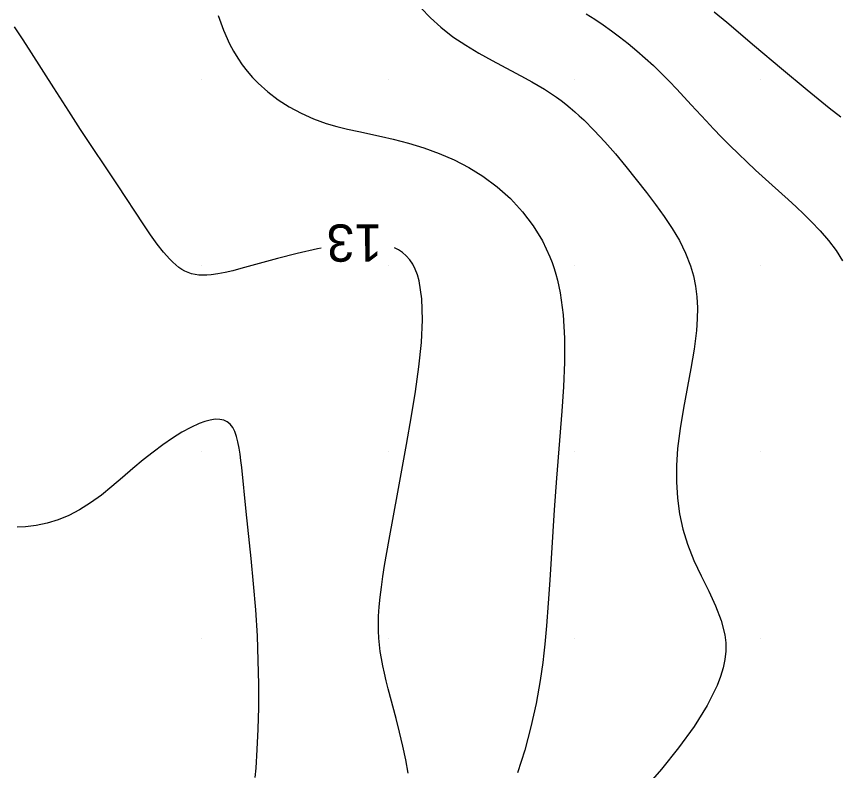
# Model space of a CAD drawing. Extents: x 2602990 to 2605851, y 618069 to 619180.
# Drawn here: x 2603060.04 to 2603104.07, y 618502.9 to 618543.37 of the extents above; entities that cross this region are included whole.
import ezdxf

# ---------------------------------------------------------------- set-up
doc = ezdxf.new("R2010")
doc.units = 0
for name, color, linetype in [('DTM Contours Major', 7, 'Continuous'), ('DTM Contours Minor', 7, 'Continuous'), ('DTM Contours Minor Text', 7, 'Continuous'), ('Exist DTM QL2 LIDAR Elevation Point', 7, 'Continuous')]:
    doc.layers.add(name, color=color, linetype=linetype)

msp = doc.modelspace()

# ---------------------------------------------------------------- linework, layer by layer
at = {"layer": 'DTM Contours Major'}
msp.add_lwpolyline([(2603097.499, 618543.623), (2603098.17, 618543.065), (2603099.669, 618541.793), (2603101.108, 618540.573), (2603102.492, 618539.429), (2603103.673, 618538.471), (2603104.295, 618537.978)], dxfattribs=at)
at = {"layer": 'DTM Contours Minor'}
for points in [[(2603081.744, 618543.84), (2603082.264, 618543.299), (2603082.825, 618542.789), (2603083.474, 618542.287), (2603084.16, 618541.826), (2603084.869, 618541.399), (2603085.586, 618541.001), (2603087.352, 618540.063), (2603087.707, 618539.868), (2603088.052, 618539.67), (2603088.388, 618539.467), (2603088.716, 618539.257), (2603089.037, 618539.038), (2603089.287, 618538.856), (2603089.533, 618538.667), (2603089.776, 618538.469), (2603090.018, 618538.262), (2603090.26, 618538.046), (2603090.501, 618537.82), (2603091.064, 618537.255), (2603091.63, 618536.643), (2603092.195, 618535.994), (2603092.757, 618535.318), (2603093.314, 618534.623), (2603093.861, 618533.92), (2603094.346, 618533.282), (2603094.811, 618532.641), (2603095.243, 618531.996), (2603095.631, 618531.342), (2603095.965, 618530.676), (2603096.232, 618529.996), (2603096.388, 618529.453), (2603096.5, 618528.898), (2603096.57, 618528.328), (2603096.6, 618527.743), (2603096.593, 618527.141), (2603096.552, 618526.52), (2603096.429, 618525.521), (2603096.254, 618524.484), (2603095.849, 618522.343), (2603095.669, 618521.26), (2603095.536, 618520.184), (2603095.478, 618519.281), (2603095.475, 618518.393), (2603095.53, 618517.523), (2603095.645, 618516.674), (2603095.823, 618515.849), (2603096.066, 618515.049), (2603096.413, 618514.184), (2603096.806, 618513.349), (2603097.207, 618512.538), (2603097.577, 618511.745), (2603097.878, 618510.963), (2603098.069, 618510.187), (2603098.116, 618509.748), (2603098.116, 618509.306), (2603098.07, 618508.86), (2603097.98, 618508.407), (2603097.845, 618507.945), (2603097.665, 618507.472), (2603097.126, 618506.388), (2603096.42, 618505.261), (2603095.587, 618504.116), (2603094.671, 618502.975), (2603093.712, 618501.86)], [(2603070.878, 618543.425), (2603071.159, 618542.639), (2603071.489, 618541.896), (2603071.699, 618541.503), (2603071.926, 618541.128), (2603072.171, 618540.771), (2603072.435, 618540.43), (2603072.717, 618540.104), (2603073.018, 618539.794), (2603073.534, 618539.331), (2603074.093, 618538.906), (2603074.691, 618538.522), (2603075.323, 618538.181), (2603075.986, 618537.885), (2603076.674, 618537.635), (2603077.243, 618537.468), (2603077.825, 618537.323), (2603078.419, 618537.192), (2603079.638, 618536.936), (2603080.261, 618536.795), (2603081.085, 618536.58), (2603081.913, 618536.324), (2603082.736, 618536.024), (2603083.544, 618535.675), (2603084.329, 618535.271), (2603085.082, 618534.808), (2603085.851, 618534.237), (2603086.564, 618533.597), (2603087.212, 618532.895), (2603087.786, 618532.135), (2603088.279, 618531.325), (2603088.682, 618530.469), (2603088.8, 618530.163), (2603088.906, 618529.851), (2603089.002, 618529.534), (2603089.087, 618529.211), (2603089.162, 618528.882), (2603089.227, 618528.546), (2603089.386, 618527.356), (2603089.457, 618526.105), (2603089.459, 618524.813), (2603089.409, 618523.499), (2603089.324, 618522.183), (2603089.036, 618518.599), (2603088.915, 618516.898), (2603088.68, 618513.127), (2603088.595, 618511.885), (2603088.5, 618510.663), (2603088.41, 618509.684), (2603088.359, 618509.197), (2603088.301, 618508.71), (2603088.236, 618508.22), (2603088.163, 618507.728), (2603087.941, 618506.494), (2603087.662, 618505.246), (2603087.328, 618504), (2603086.94, 618502.773)], [(2603090.636, 618543.521), (2603091.093, 618543.221), (2603091.542, 618542.916), (2603091.985, 618542.603), (2603092.419, 618542.281), (2603092.887, 618541.913), (2603093.346, 618541.532), (2603093.794, 618541.138), (2603094.233, 618540.733), (2603094.664, 618540.317), (2603095.086, 618539.892), (2603095.485, 618539.476), (2603096.271, 618538.627), (2603097.061, 618537.77), (2603097.463, 618537.342), (2603097.899, 618536.891), (2603098.344, 618536.444), (2603098.797, 618536.002), (2603099.255, 618535.564), (2603099.719, 618535.13), (2603100.617, 618534.314), (2603101.472, 618533.545), (2603101.892, 618533.159), (2603102.305, 618532.77), (2603102.706, 618532.375), (2603103.189, 618531.871), (2603103.637, 618531.352), (2603104.038, 618530.815), (2603104.38, 618530.257)], [(2603076.395, 618530.94), (2603076.203, 618530.905), (2603075.121, 618530.655), (2603074.058, 618530.378), (2603072.097, 618529.838), (2603071.658, 618529.726), (2603071.246, 618529.631), (2603070.861, 618529.557), (2603070.502, 618529.507), (2603070.269, 618529.488), (2603070.048, 618529.483), (2603069.838, 618529.493), (2603069.637, 618529.519), (2603069.444, 618529.562), (2603069.26, 618529.623), (2603069.087, 618529.699), (2603068.92, 618529.794), (2603068.755, 618529.905), (2603068.593, 618530.034), (2603068.432, 618530.179), (2603068.271, 618530.342), (2603067.939, 618530.719), (2603067.598, 618531.158), (2603067.245, 618531.651), (2603066.876, 618532.193), (2603065.464, 618534.337), (2603063.49, 618537.311), (2603062.854, 618538.281), (2603062.048, 618539.534), (2603060.854, 618541.424), (2603060.404, 618542.119), (2603059.943, 618542.807)], [(2603081.064, 618502.771), (2603080.946, 618503.481), (2603080.793, 618504.213), (2603080.614, 618504.955), (2603080.424, 618505.691), (2603079.998, 618507.294), (2603079.893, 618507.716), (2603079.796, 618508.127), (2603079.71, 618508.525), (2603079.637, 618508.913), (2603079.578, 618509.284), (2603079.533, 618509.65), (2603079.501, 618510.013), (2603079.482, 618510.395), (2603079.478, 618510.784), (2603079.488, 618511.183), (2603079.519, 618511.684), (2603079.569, 618512.208), (2603079.636, 618512.753), (2603079.717, 618513.322), (2603079.81, 618513.914), (2603080.05, 618515.309), (2603080.514, 618517.838), (2603080.985, 618520.404), (2603081.254, 618521.944), (2603081.465, 618523.248), (2603081.65, 618524.569), (2603081.784, 618525.866), (2603081.847, 618527.097), (2603081.814, 618528.218), (2603081.662, 618529.188), (2603081.568, 618529.513), (2603081.452, 618529.809), (2603081.315, 618530.076), (2603081.154, 618530.314), (2603080.971, 618530.524), (2603080.763, 618530.706), (2603080.55, 618530.848), (2603080.338, 618530.955)], [(2603072.859, 618502.522), (2603072.906, 618503.028), (2603072.976, 618504.026), (2603073.025, 618505.12), (2603073.052, 618506.294), (2603073.054, 618507.532), (2603073.03, 618508.817), (2603072.977, 618510.134), (2603072.889, 618511.532), (2603072.776, 618512.922), (2603072.648, 618514.279), (2603072.383, 618516.798), (2603072.137, 618519.171), (2603072.094, 618519.54), (2603072.049, 618519.884), (2603071.999, 618520.201), (2603071.934, 618520.536), (2603071.856, 618520.833), (2603071.764, 618521.092), (2603071.653, 618521.31), (2603071.52, 618521.486), (2603071.362, 618521.618), (2603071.174, 618521.707), (2603070.958, 618521.751), (2603070.715, 618521.753), (2603070.449, 618521.714), (2603070.159, 618521.637), (2603069.848, 618521.524), (2603069.4, 618521.318), (2603068.923, 618521.056), (2603068.423, 618520.744), (2603067.907, 618520.39), (2603067.381, 618519.998), (2603066.852, 618519.576), (2603066.294, 618519.106), (2603065.737, 618518.624), (2603065.175, 618518.146), (2603064.606, 618517.688), (2603064.026, 618517.263), (2603063.432, 618516.889), (2603062.861, 618516.595), (2603062.281, 618516.357), (2603061.695, 618516.175), (2603061.11, 618516.048), (2603060.531, 618515.974), (2603060.088, 618515.959)]]:
    msp.add_lwpolyline(points, dxfattribs=at)
at = {"layer": 'Exist DTM QL2 LIDAR Elevation Point'}
for p, q in [((2603070, 618540), (2603070, 618540)), ((2603080, 618540), (2603080, 618540)), ((2603090, 618540), (2603090, 618540)), ((2603100, 618540), (2603100, 618540)), ((2603070, 618530), (2603070, 618530)), ((2603080, 618530), (2603080, 618530)), ((2603090, 618530), (2603090, 618530)), ((2603100, 618530), (2603100, 618530)), ((2603070, 618520), (2603070, 618520)), ((2603080, 618520), (2603080, 618520)), ((2603090, 618520), (2603090, 618520)), ((2603100, 618520), (2603100, 618520)), ((2603070, 618510), (2603070, 618510)), ((2603080, 618510), (2603080, 618510)), ((2603090, 618510), (2603090, 618510)), ((2603100, 618510), (2603100, 618510))]:
    msp.add_line(p, q, dxfattribs=at)

# ---------------------------------------------------------------- texts
at = {"layer": 'DTM Contours Minor Text'}
msp.add_text('13', height=2, rotation=180.2201, dxfattribs=at).set_placement((2603079.669, 618532.22))

doc.saveas('drawing.dxf')
